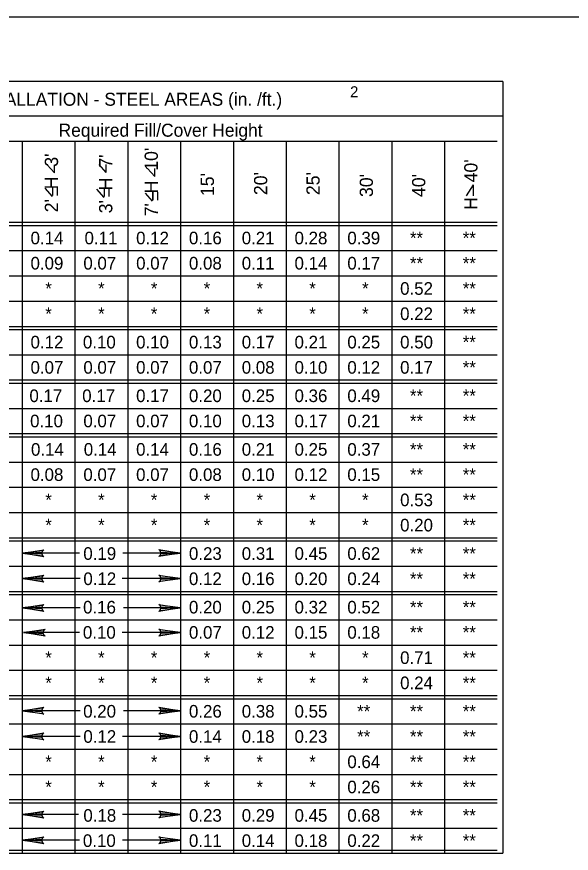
# Model space of a CAD drawing. Extents: x -22562 to -18409, y 3991 to 7171.
# Drawn here: x -20076.6 to -19955.7, y 6169.9 to 6352.4 of the extents above; entities that cross this region are included whole.
import ezdxf

# ---------------------------------------------------------------- set-up
doc = ezdxf.new("R2010")
doc.units = 0
for name, color, linetype in [('1', 7, 'Continuous'), ('2', 7, 'Continuous'), ('3', 7, 'Continuous'), ('4', 7, 'Continuous')]:
    doc.layers.add(name, color=color, linetype=linetype)

msp = doc.modelspace()

# ---------------------------------------------------------------- linework, layer by layer
at = {"layer": '1'}
for p, q in [((-20068.35, 6318.32), (-20069.91, 6320.09)), ((-20068.35, 6318.32), (-20068.35, 6320.08)), ((-20057.06, 6318.38), (-20058.62, 6320.15)), ((-20057.06, 6318.38), (-20057.06, 6320.14)), ((-20046.48, 6317.49), (-20048.05, 6319.26)), ((-20046.48, 6317.49), (-20046.48, 6319.25)), ((-20068.8, 6313.19), (-20070.37, 6314.95)), ((-19977.03, 6315.71), (-19978.6, 6313.28)), ((-19977.03, 6315.71), (-19977.03, 6313.3)), ((-20057.51, 6312.97), (-20059.08, 6314.74)), ((-20046.94, 6312.13), (-20048.5, 6313.9))]:
    msp.add_line(p, q, dxfattribs=at)
at = {"layer": '2'}
for p, q in [((-20344.85, 6352.37), (-19558.85, 6352.37)), ((-19970.6, 6338.24), (-20138.7, 6338.24)), ((-19970.6, 6338.24), (-19970.6, 6169.92)), ((-19970.6, 6330.67), (-20138.7, 6330.67)), ((-19971.79, 6325.17), (-20138.7, 6325.17)), ((-20075.39, 6325.17), (-20075.39, 6169.92)), ((-20063.88, 6325.17), (-20063.88, 6169.92)), ((-20052.37, 6325.17), (-20052.37, 6169.92)), ((-20040.86, 6325.17), (-20040.86, 6169.92)), ((-20029.34, 6325.17), (-20029.34, 6169.92)), ((-20017.83, 6325.17), (-20017.83, 6169.92)), ((-20006.33, 6325.17), (-20006.33, 6169.92)), ((-19994.81, 6325.17), (-19994.81, 6169.92)), ((-19983.3, 6325.17), (-19983.3, 6169.92)), ((-20138.7, 6307.55), (-19971.79, 6307.55)), ((-20138.7, 6306.86), (-19971.79, 6306.86)), ((-20138.7, 6301.36), (-19971.79, 6301.36)), ((-20138.7, 6295.85), (-19971.79, 6295.85)), ((-20138.7, 6290.34), (-19971.79, 6290.34)), ((-20138.7, 6284.84), (-19971.79, 6284.84)), ((-20138.7, 6284.84), (-19971.79, 6284.84)), ((-20138.7, 6284.15), (-19971.79, 6284.15)), ((-20138.7, 6278.64), (-19971.79, 6278.64)), ((-20138.7, 6273.14), (-19971.79, 6273.14)), ((-20138.7, 6273.14), (-19971.79, 6273.14)), ((-20138.7, 6272.45), (-19971.79, 6272.45)), ((-20138.7, 6266.95), (-19971.79, 6266.95)), ((-20138.7, 6261.44), (-19971.79, 6261.44)), ((-20138.7, 6261.44), (-19971.79, 6261.44)), ((-20138.7, 6260.75), (-19971.79, 6260.75)), ((-20138.7, 6255.24), (-19971.79, 6255.24)), ((-20138.7, 6249.74), (-19971.79, 6249.74)), ((-20138.7, 6244.23), (-19971.79, 6244.23)), ((-20138.7, 6244.23), (-19971.79, 6244.23)), ((-20138.7, 6238.73), (-19971.79, 6238.73)), ((-20138.7, 6238.04), (-19971.79, 6238.04)), ((-20062.91, 6235.37), (-20075.39, 6235.37)), ((-20040.86, 6235.37), (-20053.45, 6235.37)), ((-20138.7, 6232.53), (-19971.79, 6232.53)), ((-20062.76, 6229.83), (-20075.39, 6229.83)), ((-20040.86, 6229.83), (-20053.59, 6229.83)), ((-20138.7, 6227.03), (-19971.79, 6227.03)), ((-20138.7, 6226.34), (-19971.79, 6226.34)), ((-20062.76, 6223.43), (-20075.39, 6223.43)), ((-20040.86, 6223.43), (-20053.3, 6223.43)), ((-20138.7, 6220.83), (-19971.79, 6220.83)), ((-20062.91, 6218.04), (-20075.1, 6218.04)), ((-20040.86, 6218.04), (-20053.59, 6218.04)), ((-20138.7, 6215.33), (-19971.79, 6215.33)), ((-20138.7, 6209.82), (-19971.79, 6209.82)), ((-20138.7, 6204.32), (-19971.79, 6204.32)), ((-20138.7, 6203.63), (-19971.79, 6203.63)), ((-20062.75, 6201), (-20075.39, 6201)), ((-20040.86, 6201), (-20053.31, 6201)), ((-20138.7, 6198.13), (-19971.79, 6198.13)), ((-20062.75, 6195.4), (-20075.39, 6195.4)), ((-20040.86, 6195.4), (-20053.54, 6195.4)), ((-20138.7, 6192.62), (-19971.79, 6192.62)), ((-20138.7, 6187.11), (-19971.79, 6187.11)), ((-20138.7, 6181.61), (-19971.79, 6181.61)), ((-20138.7, 6181.61), (-19971.79, 6181.61)), ((-20138.7, 6180.92), (-19971.79, 6180.92)), ((-20063.1, 6178.36), (-20075.39, 6178.36)), ((-20040.86, 6178.36), (-20053.54, 6178.36)), ((-20138.7, 6175.42), (-19971.79, 6175.42)), ((-20062.87, 6172.76), (-20075.39, 6172.76)), ((-20040.86, 6172.76), (-20053.54, 6172.76)), ((-20138.7, 6170.6), (-19971.79, 6170.6)), ((-20138.7, 6169.92), (-19970.6, 6169.92)), ((-20138.7, 6169.91), (-19971.79, 6169.91)), ((-20138.7, 6169.91), (-19971.79, 6169.91))]:
    msp.add_line(p, q, dxfattribs=at)
for points in [[(-20070.86, 6234.8), (-20071.03, 6235.13), (-20075.39, 6235.37), (-20070.86, 6234.8), (-20070.63, 6234.6), (-20075.39, 6235.37), (-20071.04, 6235.58), (-20070.88, 6235.9), (-20075.39, 6235.37), (-20070.63, 6236.12), (-20070.88, 6235.9)], [(-20045.38, 6235.93), (-20045.21, 6235.61), (-20040.86, 6235.37), (-20045.38, 6235.93), (-20045.61, 6236.13), (-20040.86, 6235.37), (-20045.21, 6235.15), (-20045.37, 6234.83), (-20040.86, 6235.37), (-20045.61, 6234.61), (-20045.37, 6234.83)], [(-20070.86, 6229.26), (-20071.03, 6229.59), (-20075.39, 6229.83), (-20070.86, 6229.26), (-20070.63, 6229.07), (-20075.39, 6229.83), (-20071.04, 6230.05), (-20070.88, 6230.37), (-20075.39, 6229.83), (-20070.63, 6230.59), (-20070.88, 6230.37)], [(-20045.38, 6230.4), (-20045.21, 6230.07), (-20040.86, 6229.83), (-20045.38, 6230.4), (-20045.61, 6230.6), (-20040.86, 6229.83), (-20045.21, 6229.62), (-20045.37, 6229.29), (-20040.86, 6229.83), (-20045.61, 6229.08), (-20045.37, 6229.29)], [(-20070.86, 6222.86), (-20071.03, 6223.19), (-20075.39, 6223.43), (-20070.86, 6222.86), (-20070.63, 6222.66), (-20075.39, 6223.43), (-20071.04, 6223.64), (-20070.88, 6223.96), (-20075.39, 6223.43), (-20070.63, 6224.18), (-20070.88, 6223.96)], [(-20045.38, 6223.99), (-20045.21, 6223.67), (-20040.86, 6223.43), (-20045.38, 6223.99), (-20045.61, 6224.19), (-20040.86, 6223.43), (-20045.21, 6223.21), (-20045.37, 6222.89), (-20040.86, 6223.43), (-20045.61, 6222.67), (-20045.37, 6222.89)], [(-20070.57, 6217.47), (-20070.74, 6217.8), (-20075.1, 6218.04), (-20070.57, 6217.47), (-20070.34, 6217.27), (-20075.1, 6218.04), (-20070.75, 6218.25), (-20070.59, 6218.58), (-20075.1, 6218.04), (-20070.34, 6218.79), (-20070.59, 6218.58)], [(-20045.38, 6218.61), (-20045.21, 6218.28), (-20040.86, 6218.04), (-20045.38, 6218.61), (-20045.61, 6218.8), (-20040.86, 6218.04), (-20045.21, 6217.82), (-20045.37, 6217.5), (-20040.86, 6218.04), (-20045.61, 6217.28), (-20045.37, 6217.5)], [(-20070.86, 6200.43), (-20071.03, 6200.76), (-20075.39, 6201), (-20070.86, 6200.43), (-20070.63, 6200.23), (-20075.39, 6201), (-20071.04, 6201.22), (-20070.88, 6201.54), (-20075.39, 6201), (-20070.63, 6201.76), (-20070.88, 6201.54)], [(-20045.38, 6201.57), (-20045.21, 6201.24), (-20040.86, 6201), (-20045.38, 6201.57), (-20045.61, 6201.77), (-20040.86, 6201), (-20045.21, 6200.79), (-20045.37, 6200.46), (-20040.86, 6201), (-20045.61, 6200.24), (-20045.37, 6200.46)], [(-20070.86, 6194.83), (-20071.03, 6195.16), (-20075.39, 6195.4), (-20070.86, 6194.83), (-20070.63, 6194.63), (-20075.39, 6195.4), (-20071.04, 6195.62), (-20070.88, 6195.94), (-20075.39, 6195.4), (-20070.63, 6196.16), (-20070.88, 6195.94)], [(-20045.38, 6195.97), (-20045.21, 6195.64), (-20040.86, 6195.4), (-20045.38, 6195.97), (-20045.61, 6196.17), (-20040.86, 6195.4), (-20045.21, 6195.18), (-20045.37, 6194.86), (-20040.86, 6195.4), (-20045.61, 6194.64), (-20045.37, 6194.86)], [(-20070.86, 6177.79), (-20071.03, 6178.12), (-20075.39, 6178.36), (-20070.86, 6177.79), (-20070.63, 6177.6), (-20075.39, 6178.36), (-20071.04, 6178.58), (-20070.88, 6178.9), (-20075.39, 6178.36), (-20070.63, 6179.12), (-20070.88, 6178.9)], [(-20045.38, 6178.93), (-20045.21, 6178.6), (-20040.86, 6178.36), (-20045.38, 6178.93), (-20045.61, 6179.13), (-20040.86, 6178.36), (-20045.21, 6178.15), (-20045.37, 6177.82), (-20040.86, 6178.36), (-20045.61, 6177.61), (-20045.37, 6177.82)], [(-20070.86, 6172.19), (-20071.03, 6172.52), (-20075.39, 6172.76), (-20070.86, 6172.19), (-20070.63, 6171.99), (-20075.39, 6172.76), (-20071.04, 6172.98), (-20070.88, 6173.3), (-20075.39, 6172.76), (-20070.63, 6173.52), (-20070.88, 6173.3)], [(-20045.38, 6173.33), (-20045.21, 6173), (-20040.86, 6172.76), (-20045.38, 6173.33), (-20045.61, 6173.53), (-20040.86, 6172.76), (-20045.21, 6172.55), (-20045.37, 6172.22), (-20040.86, 6172.76), (-20045.61, 6172), (-20045.37, 6172.22)]]:
    msp.add_lwpolyline(points, dxfattribs=at)

# ---------------------------------------------------------------- texts
at = {"layer": '1'}
for s, height, p in [("15'", 2.883, (-20033.57, 6313.25)), ("20'", 2.883, (-20021.95, 6313.46)), ("25'", 2.883, (-20010.53, 6313.46)), ("30'", 2.883, (-19998.91, 6313.04)), ("40'", 2.883, (-19987.49, 6313.04)), ('=', 2.88, (-20066.86, 6313.16)), ('=', 2.88, (-20055.57, 6312.94)), ('=', 2.88, (-20044.99, 6312.1))]:
    msp.add_text(s, height=height, rotation=90, dxfattribs=at).set_placement(p)
at = {"layer": '2'}
for s, height, p in [('2', 2.42, (-20003.89, 6334.78)), ('TYPE A STANDARD INSTALLATION - STEEL AREAS (in. /ft.)', 2.8357, (-20124.26, 6332.95)), ('Required Fill/Cover Height', 2.8357, (-20067.44, 6326.2))]:
    msp.add_text(s, height=height, dxfattribs=at).set_placement(p)
at = {"layer": '3'}
for s, height, p in [('0.14', 2.751, (-20073.55, 6302.73)), ('0.11', 2.751, (-20061.79, 6302.73)), ('0.12', 2.751, (-20050.54, 6302.73)), ('0.16', 2.751, (-20039.02, 6302.73)), ('0.21', 2.751, (-20027.51, 6302.73)), ('0.28', 2.751, (-20016, 6302.73)), ('0.39', 2.751, (-20004.49, 6302.73)), ('**', 2.751, (-19990.84, 6302.73)), ('**', 2.751, (-19979.33, 6302.73)), ('0.09', 2.751, (-20073.56, 6297.23)), ('0.07', 2.751, (-20062.04, 6297.23)), ('0.07', 2.751, (-20050.53, 6297.23)), ('0.08', 2.751, (-20039.02, 6297.23)), ('0.11', 2.751, (-20027.51, 6297.23)), ('0.14', 2.751, (-20016, 6297.23)), ('0.17', 2.751, (-20004.49, 6297.23)), ('**', 2.751, (-19990.84, 6297.23)), ('**', 2.751, (-19979.33, 6297.23)), ('*', 2.75, (-20070.34, 6291.72)), ('*', 2.75, (-20058.83, 6291.72)), ('*', 2.75, (-20047.33, 6291.72)), ('*', 2.75, (-20035.81, 6291.72)), ('*', 2.75, (-20024.3, 6291.72)), ('*', 2.75, (-20012.79, 6291.72)), ('*', 2.75, (-20001.28, 6291.72)), ('0.52', 2.751, (-19992.98, 6291.72)), ('**', 2.751, (-19979.33, 6291.72)), ('*', 2.75, (-20070.34, 6286.21)), ('*', 2.75, (-20058.83, 6286.21)), ('*', 2.75, (-20047.33, 6286.21)), ('*', 2.75, (-20035.81, 6286.21)), ('*', 2.75, (-20024.3, 6286.21)), ('*', 2.75, (-20012.79, 6286.21)), ('*', 2.75, (-20001.28, 6286.21)), ('0.22', 2.751, (-19992.98, 6286.21)), ('**', 2.751, (-19979.33, 6286.21)), ('0.12', 2.751, (-20073.56, 6280.02)), ('0.10', 2.751, (-20062.14, 6280.02)), ('0.10', 2.751, (-20050.54, 6280.02)), ('0.13', 2.751, (-20039.02, 6280.02)), ('0.17', 2.751, (-20027.51, 6280.02)), ('0.21', 2.751, (-20016, 6280.02)), ('0.25', 2.751, (-20004.49, 6280.02)), ('0.50', 2.751, (-19992.98, 6280.02)), ('**', 2.751, (-19979.33, 6280.02)), ('0.07', 2.751, (-20073.56, 6274.51)), ('0.07', 2.751, (-20062.04, 6274.51)), ('0.07', 2.751, (-20050.54, 6274.51)), ('0.07', 2.751, (-20039.02, 6274.51)), ('0.08', 2.751, (-20027.51, 6274.51)), ('0.10', 2.751, (-20016, 6274.51)), ('0.12', 2.751, (-20004.49, 6274.51)), ('0.17', 2.751, (-19992.98, 6274.51)), ('**', 2.751, (-19979.33, 6274.51)), ('0.17', 2.751, (-20073.8, 6268.32)), ('0.17', 2.751, (-20062.29, 6268.32)), ('0.17', 2.751, (-20050.54, 6268.32)), ('0.20', 2.751, (-20039.02, 6268.32)), ('0.25', 2.751, (-20027.51, 6268.32)), ('0.36', 2.751, (-20016, 6268.32)), ('0.49', 2.751, (-20004.49, 6268.32)), ('**', 2.751, (-19990.84, 6268.32)), ('**', 2.751, (-19979.33, 6268.32)), ('0.10', 2.751, (-20073.65, 6262.82)), ('0.07', 2.751, (-20062.04, 6262.82)), ('0.07', 2.751, (-20050.54, 6262.82)), ('0.10', 2.751, (-20039.02, 6262.82)), ('0.13', 2.751, (-20027.51, 6262.82)), ('0.17', 2.751, (-20016, 6262.82)), ('0.21', 2.751, (-20004.49, 6262.82)), ('**', 2.751, (-19990.84, 6262.82)), ('**', 2.751, (-19979.33, 6262.82)), ('0.14', 2.751, (-20073.46, 6256.62)), ('0.14', 2.751, (-20061.95, 6256.62)), ('0.14', 2.751, (-20050.54, 6256.62)), ('0.16', 2.751, (-20039.02, 6256.62)), ('0.21', 2.751, (-20027.51, 6256.62)), ('0.25', 2.751, (-20016, 6256.62)), ('0.37', 2.751, (-20004.49, 6256.62)), ('**', 2.751, (-19990.84, 6256.62)), ('**', 2.751, (-19979.33, 6256.62)), ('0.08', 2.751, (-20073.56, 6251.12)), ('0.07', 2.751, (-20062.04, 6251.12)), ('0.07', 2.751, (-20050.54, 6251.12)), ('0.08', 2.751, (-20039.02, 6251.12)), ('0.10', 2.751, (-20027.51, 6251.12)), ('0.12', 2.751, (-20016, 6251.12)), ('0.15', 2.751, (-20004.49, 6251.12)), ('**', 2.751, (-19990.84, 6251.12)), ('**', 2.751, (-19979.33, 6251.12)), ('*', 2.75, (-20070.34, 6245.61)), ('*', 2.75, (-20058.83, 6245.61)), ('*', 2.75, (-20047.33, 6245.61)), ('*', 2.75, (-20035.81, 6245.61)), ('*', 2.75, (-20024.3, 6245.61)), ('*', 2.75, (-20012.79, 6245.61)), ('*', 2.75, (-20001.28, 6245.61)), ('0.53', 2.751, (-19992.98, 6245.61)), ('**', 2.751, (-19979.33, 6245.61)), ('*', 2.75, (-20070.34, 6240.11)), ('*', 2.75, (-20058.83, 6240.11)), ('*', 2.75, (-20047.33, 6240.11)), ('*', 2.75, (-20035.81, 6240.11)), ('*', 2.75, (-20024.3, 6240.11)), ('*', 2.75, (-20012.79, 6240.11)), ('*', 2.75, (-20001.28, 6240.11)), ('0.20', 2.751, (-19992.98, 6240.11)), ('**', 2.751, (-19979.33, 6240.11)), ('0.19', 2.753, (-20062.05, 6233.91)), ('0.23', 2.751, (-20039.02, 6233.91)), ('0.31', 2.751, (-20027.51, 6233.91)), ('0.45', 2.751, (-20016, 6233.91)), ('0.62', 2.751, (-20004.49, 6233.91)), ('**', 2.751, (-19990.84, 6233.91)), ('**', 2.751, (-19979.33, 6233.91)), ('0.12', 2.751, (-20062.04, 6228.41)), ('0.12', 2.751, (-20039.02, 6228.41)), ('0.16', 2.751, (-20027.51, 6228.41)), ('0.20', 2.751, (-20016, 6228.41)), ('0.24', 2.751, (-20004.49, 6228.41)), ('**', 2.751, (-19990.84, 6228.41)), ('**', 2.751, (-19979.33, 6228.41)), ('0.16', 2.751, (-20062.1, 6222.21)), ('0.20', 2.751, (-20039.02, 6222.21)), ('0.25', 2.751, (-20027.51, 6222.21)), ('0.32', 2.751, (-20016, 6222.21)), ('0.52', 2.751, (-20004.49, 6222.21)), ('**', 2.751, (-19990.84, 6222.21)), ('**', 2.751, (-19979.33, 6222.21)), ('0.10', 2.751, (-20062.14, 6216.71)), ('0.07', 2.751, (-20039.02, 6216.71)), ('0.12', 2.751, (-20027.51, 6216.71)), ('0.15', 2.751, (-20016, 6216.71)), ('0.18', 2.751, (-20004.49, 6216.71)), ('**', 2.751, (-19990.84, 6216.71)), ('**', 2.751, (-19979.33, 6216.71)), ('*', 2.75, (-20070.34, 6211.2)), ('*', 2.75, (-20058.83, 6211.2)), ('*', 2.75, (-20047.33, 6211.2)), ('*', 2.75, (-20035.81, 6211.2)), ('*', 2.75, (-20024.3, 6211.2)), ('*', 2.75, (-20012.79, 6211.2)), ('*', 2.75, (-20001.28, 6211.2)), ('0.71', 2.751, (-19992.98, 6211.2)), ('**', 2.751, (-19979.33, 6211.2)), ('*', 2.75, (-20070.34, 6205.7)), ('*', 2.75, (-20058.83, 6205.7)), ('*', 2.75, (-20047.33, 6205.7)), ('*', 2.75, (-20035.81, 6205.7)), ('*', 2.75, (-20024.3, 6205.7)), ('*', 2.75, (-20012.79, 6205.7)), ('*', 2.75, (-20001.28, 6205.7)), ('0.24', 2.751, (-19992.98, 6205.7)), ('**', 2.751, (-19979.33, 6205.7)), ('0.20', 2.751, (-20062.08, 6199.5)), ('0.26', 2.751, (-20039.02, 6199.5)), ('0.38', 2.751, (-20027.51, 6199.5)), ('0.55', 2.751, (-20016, 6199.5)), ('**', 2.751, (-20002.35, 6199.5)), ('**', 2.751, (-19990.84, 6199.5)), ('**', 2.751, (-19979.33, 6199.5)), ('0.12', 2.751, (-20062.04, 6194)), ('0.14', 2.751, (-20039.02, 6194)), ('0.18', 2.751, (-20027.51, 6194)), ('0.23', 2.751, (-20016, 6194)), ('**', 2.751, (-20002.35, 6194)), ('**', 2.751, (-19990.84, 6194)), ('**', 2.751, (-19979.33, 6194)), ('*', 2.75, (-20070.34, 6188.49)), ('*', 2.75, (-20058.83, 6188.49)), ('*', 2.75, (-20047.33, 6188.49)), ('*', 2.75, (-20035.81, 6188.49)), ('*', 2.75, (-20024.3, 6188.49)), ('*', 2.75, (-20012.79, 6188.49)), ('0.64', 2.751, (-20004.49, 6188.49)), ('**', 2.751, (-19990.84, 6188.49)), ('**', 2.751, (-19979.33, 6188.49)), ('*', 2.75, (-20070.34, 6182.99)), ('*', 2.75, (-20058.83, 6182.99)), ('*', 2.75, (-20047.33, 6182.99)), ('*', 2.75, (-20035.81, 6182.99)), ('*', 2.75, (-20024.3, 6182.99)), ('*', 2.75, (-20012.79, 6182.99)), ('0.26', 2.751, (-20004.49, 6182.99)), ('**', 2.751, (-19990.84, 6182.99)), ('**', 2.751, (-19979.33, 6182.99)), ('0.18', 2.751, (-20062.04, 6176.79)), ('0.23', 2.751, (-20039.02, 6176.79)), ('0.29', 2.751, (-20027.51, 6176.79)), ('0.45', 2.751, (-20016, 6176.79)), ('0.68', 2.751, (-20004.49, 6176.79)), ('**', 2.751, (-19990.84, 6176.79)), ('**', 2.751, (-19979.33, 6176.79)), ('0.10', 2.751, (-20062.14, 6171.29)), ('0.11', 2.751, (-20039.02, 6171.29)), ('0.14', 2.751, (-20027.51, 6171.29)), ('0.18', 2.751, (-20016, 6171.29)), ('0.22', 2.751, (-20004.49, 6171.29)), ('**', 2.751, (-19990.84, 6171.29)), ('**', 2.751, (-19979.33, 6171.29))]:
    msp.add_text(s, height=height, dxfattribs=at).set_placement(p)
at = {"layer": '4'}
for s, p in [("2'  H  3'", (-20067.56, 6309.71)), ("7'  H  10'", (-20045.8, 6308.82)), ("3'  H  7'", (-20055.72, 6309.49)), ("H   40'", (-19976.12, 6310.23))]:
    msp.add_text(s, height=2.883, rotation=90, dxfattribs=at).set_placement(p)

doc.saveas('drawing.dxf')
